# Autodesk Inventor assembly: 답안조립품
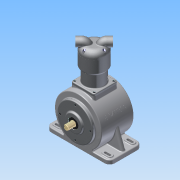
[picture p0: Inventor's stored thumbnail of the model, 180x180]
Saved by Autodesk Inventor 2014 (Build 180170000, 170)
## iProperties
Created: 2015-06
Part Number: 답안조립품
Document SubType Name: Assembly
Designer: Administrator
Author: Administrator
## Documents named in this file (15)
- C:\Users\Administrator\Desktop\450605V1042\답안조립품.iam
- C:\Users\Administrator\Desktop\450605V1042\본체.ipt
- C:\Users\Administrator\Desktop\450605V1042\베어링 6204.ipt
- C:\Users\Administrator\Desktop\450605V1042\메인커버.ipt
- C:\Users\Administrator\Desktop\450605V1042\오일실.ipt
- C:\Users\Administrator\Desktop\450605V1042\크랭크 서브축.ipt
- C:\Users\Administrator\Desktop\450605V1042\커넥팅 로드.ipt
- C:\Users\Administrator\Desktop\450605V1042\메인 크랭크 축-구동부.ipt
- C:\Users\Administrator\Desktop\450605V1042\베어링 NA 4902.ipt
- C:\Users\Administrator\Desktop\450605V1042\실린더.ipt
- C:\Users\Administrator\Desktop\450605V1042\피스톤.ipt
- C:\Users\Administrator\Desktop\450605V1042\피스톤 핀.ipt
- C:\Users\Administrator\Desktop\450605V1042\실린더헤드.ipt
- C:\Users\Administrator\Desktop\450605V1042\M5x0.8.ipt
- C:\Users\Administrator\Desktop\450605V1042\M4x0.7.ipt
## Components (14 placed, 4 different names)
1. 피스톤:1
2. 피스톤 핀:1
3. M4x0.7:1
4. M4x0.7:2
5. M4x0.7:3
6. M4x0.7:4
7. M5x0.8:1
8. M5x0.8:2
9. M5x0.8:3
10. M5x0.8:4
11. M4x0.7:5
12. M4x0.7:6
13. M4x0.7:7
14. M4x0.7:8
